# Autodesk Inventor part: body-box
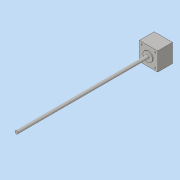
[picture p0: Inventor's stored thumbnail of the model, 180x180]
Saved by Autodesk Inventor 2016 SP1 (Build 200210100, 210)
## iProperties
Created: 2016-06
Part Number: body-box
Material: Generic
Document SubType Name: Modeling
Designer: Mohamed A.
Density: 1 g/cm^3
Appearance: Default
Author: Mohamed A.
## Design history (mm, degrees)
sketch "Sketch1"
  geometry: L1 (-21, 21)-(21, 21); L2 (21, 21)-(21, -21); L3 (21, -21)-(-21, -21); L4 (-21, -21)-(-21, 21); L5 (-21, 21)-(21, -21); L6 (21, 21)-(-21, -21); 1 further point
  constraints: 12 end point, 2 midpoint, 2 parallel, 1 horizontal, 1 perpendicular
  dimensions: "d0" = 42 distance of L2.end L3.end; "d1" = 42 distance of L1.end L2.end
extrude "Extrusion1" new body sketch "Sketch1" distance "d2" = 34; taper "d3" = 0 deg
sketch "Sketch2"
  geometry: C1 r 1.5 at (-15.5, 15.5); C2 r 1.5 at (15.5, 15.5); C3 r 1.5 at (15.5, -15.5); C4 r 1.5 at (-15.5, -15.5); 1 further point
  constraints: 4 centre point
  dimensions: "d4" = 3 diameter of C1; "d5" = 3 diameter of C2; "d6" = 3 diameter of C3; "d7" = 3 diameter of C4; "d8" = 31 distance of C1.centre C2.centre; "d9" = 31 distance of C3.centre C2.centre; "d10" = 31 distance of C1.centre C4.centre (= d9); "d11" = 31 distance of C4.centre C3.centre (= d8); "d12" = 15.5 horizontal distance of C2.centre point (0, 0) (= 0.5 x d8); "d13" = 15.5 horizontal distance of C1.centre point (0, 0) (= 0.5 x d10); "d14" = 15.5 horizontal distance of point (0, 0) C2.centre (= d13); "d15" = 15.5 horizontal distance of point (0, 0) C4.centre
extrude "Extrusion2" cut sketch "Sketch2" distance "d17" = 5; taper "d18" = 0 deg
sketch "Sketch3"
  geometry: C1 r 11 at (0, 0); 1 further point
  constraints: 1 centre point, 1 coincident
  dimensions: "d19" = 22 diameter of C1
extrude "Extrusion3" join sketch "Sketch3" distance "d20" = 2; taper "d21" = 0 deg
sketch "Sketch4"
  geometry: C1 r 3.5 at (0, 0); 1 further point
  constraints: 1 centre point, 1 coincident
  dimensions: "d22" = 7 diameter of C1
extrude "Extrusion4" join sketch "Sketch4" distance "d23" = 300; taper "d24" = 0 deg
body "Solid1"
